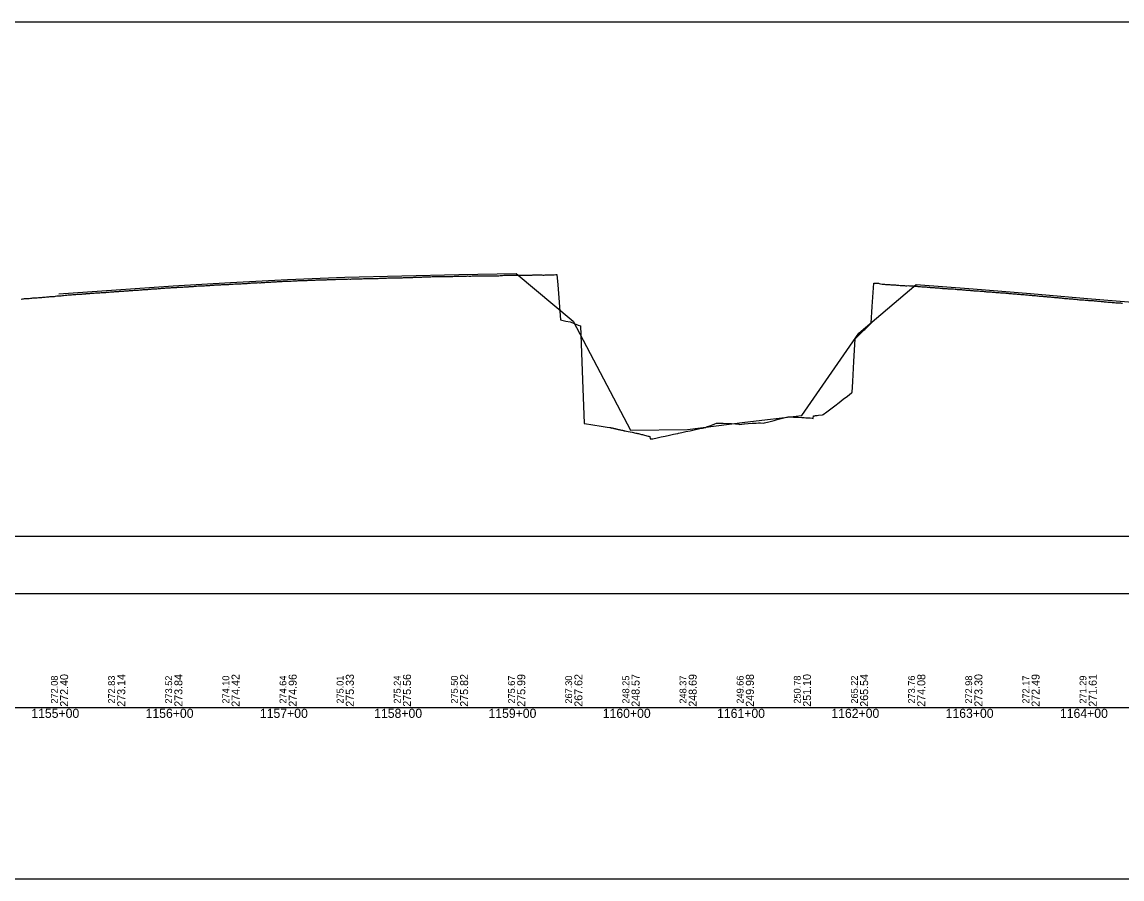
# Model space of a CAD drawing. Extents: x 2898 to 49495, y -15038 to -13538.
# Drawn here: x 4821 to 5783, y -15038 to -14288 of the extents above; entities that cross this region are included whole.
import ezdxf

# ---------------------------------------------------------------- set-up
doc = ezdxf.new("R2010")
doc.units = 0
for name, color, linetype in [('RD_DDB_Profile_EX', 7, 'Continuous'), ('RD_DDB_Profile_PR', 7, 'Continuous'), ('RD_DDB_StaTX', 7, 'Continuous'), ('RD_DDB_StripGrade', 7, 'Continuous'), ('RD_GPK_Profile_Cell', 7, 'Continuous'), ('RD_SHT_ShtClip', 7, 'Continuous')]:
    doc.layers.add(name, color=color, linetype=linetype)

msp = doc.modelspace()

# ---------------------------------------------------------------- linework, layer by layer
at = {"layer": 'RD_DDB_Profile_EX'}
for points in [[(5085.43, -14513.98), (5086.43, -14513.98), (5086.86, -14513.98), (5087.43, -14513.98), (5088.43, -14513.93), (5089.43, -14513.83), (5090.49, -14513.78), (5091.43, -14513.78), (5092.43, -14513.73), (5093.43, -14513.73), (5094.43, -14513.68), (5095.43, -14513.68), (5096.43, -14513.64), (5097.78, -14513.53), (5098.76, -14513.53), (5099.76, -14513.53), (5100.78, -14513.47), (5101.35, -14513.47), (5101.76, -14513.47), (5102.76, -14513.42), (5103.76, -14513.41), (5104.97, -14513.41), (5105.76, -14513.4), (5106.76, -14513.35), (5107.76, -14513.4), (5108.76, -14513.39), (5109.76, -14513.34), (5110.76, -14513.29), (5111.76, -14513.29), (5112.22, -14513.29), (5112.76, -14513.29), (5113.76, -14513.24), (5114.76, -14513.19), (5115.84, -14513.18), (5116.77, -14513.18), (5117.77, -14513.18), (5118.77, -14513.13), (5119.77, -14513.08), (5120.77, -14513.08), (5121.77, -14513.08), (5122.77, -14513.03), (5123.08, -14513.02), (5123.77, -14512.98), (5124.77, -14512.98), (5125.77, -14512.99), (5126.77, -14512.89), (5127.77, -14512.94), (5128.77, -14512.94), (5129.77, -14512.89), (5130.33, -14512.87), (5130.77, -14512.84), (5131.75, -14512.8), (5132.75, -14512.8), (5133.95, -14512.79), (5134.75, -14512.76), (5135.75, -14512.66), (5136.27, -14512.64), (5137.19, -14512.6), (5137.57, -14512.58), (5138.12, -14512.56), (5139.03, -14512.56), (5139.94, -14512.56), (5141.19, -14512.48), (5141.85, -14512.47), (5142.76, -14512.47), (5143.68, -14512.46), (5144.82, -14512.41), (5145.55, -14512.4), (5146.51, -14512.49), (5146.87, -14512.49), (5147.88, -14512.48), (5148.44, -14512.42), (5148.87, -14512.38), (5149.87, -14512.32), (5150.88, -14512.32), (5152.06, -14512.3), (5152.87, -14512.26), (5153.86, -14512.25), (5154.87, -14512.2), (5155.87, -14512.19), (5156.86, -14512.14), (5157.87, -14512.14), (5158.87, -14512.13), (5159.3, -14512.09), (5159.86, -14512.03), (5160.87, -14511.98), (5161.86, -14511.97), (5162.93, -14511.97), (5163.87, -14511.91), (5164.9, -14511.91), (5165.87, -14511.86), (5166.55, -14511.82), (5166.87, -14511.81), (5167.87, -14511.81), (5168.87, -14511.75), (5170.17, -14511.7), (5170.87, -14511.7), (5171.87, -14511.6), (5172.86, -14511.6), (5173.87, -14511.6), (5174.87, -14511.6)], [(5174.87, -14511.6), (5175.86, -14511.55), (5176.87, -14511.4), (5177.41, -14511.4), (5177.87, -14511.4), (5178.87, -14511.35), (5179.87, -14511.2), (5181.04, -14511.2), (5181.87, -14511.2), (5182.87, -14511.19), (5183.87, -14511.18), (5184.88, -14511.12), (5185.88, -14511.16), (5186.88, -14511.15), (5187.87, -14511.14), (5188.28, -14511.16), (5188.88, -14511.18), (5189.88, -14511.13), (5190.88, -14511.12), (5191.9, -14511.11), (5192.88, -14511.1), (5193.89, -14511.09), (5194.89, -14511.08), (5195.52, -14511.08), (5195.89, -14511.07), (5196.89, -14511.07), (5197.89, -14511.06), (5199.15, -14510.99), (5199.89, -14510.95), (5200.89, -14510.9), (5201.89, -14510.89), (5202.89, -14510.93), (5203.9, -14510.98), (5204.89, -14510.97), (5205.9, -14510.97), (5206.39, -14510.89), (5206.9, -14510.82), (5207.9, -14510.81), (5208.9, -14510.85), (5210.01, -14510.84), (5210.9, -14510.75), (5211.9, -14510.8), (5212.9, -14510.84), (5213.9, -14510.79), (5214.9, -14510.69), (5215.9, -14510.64), (5216.9, -14510.64), (5217.26, -14510.64), (5217.9, -14510.64), (5218.9, -14510.64), (5219.91, -14510.59), (5220.9, -14510.53), (5221.9, -14510.58), (5222.91, -14510.59), (5223.32, -14510.58), (5224.5, -14510.52), (5225.32, -14510.51), (5226.34, -14510.56), (5227.34, -14510.59), (5228.35, -14510.64), (5229.35, -14510.67), (5230.35, -14510.71), (5231.35, -14510.66), (5231.74, -14510.65), (5232.35, -14510.65), (5233.35, -14510.64), (5234.35, -14510.55), (5235.37, -14510.54), (5236.35, -14510.58), (5237.35, -14510.52), (5238.35, -14510.48), (5239.35, -14510.37), (5240.35, -14510.28), (5241.36, -14510.19), (5242.61, -14510.16), (5243.36, -14510.12), (5244.36, -14510.11), (5245.36, -14510.15), (5246.44, -14510.07), (5247.36, -14510.02), (5248.36, -14510.02), (5249.36, -14510.06), (5249.85, -14510.08), (5250.36, -14510.1), (5251.36, -14510.14), (5252.36, -14510.1), (5253.47, -14510.14), (5254.36, -14510.09), (5255.36, -14510.04), (5256.36, -14510), (5257.35, -14510.04), (5258.35, -14510), (5259.35, -14509.94), (5260.35, -14509.94), (5260.72, -14509.96), (5261.35, -14509.98), (5262.35, -14509.89), (5263.35, -14509.89), (5264.35, -14509.89), (5265.35, -14509.94), (5266.35, -14509.94)], [(5266.35, -14509.94), (5267.35, -14509.89), (5267.96, -14509.86), (5268.35, -14509.84), (5269.35, -14509.84), (5270.43, -14509.85), (5270.81, -14509.84), (5271.81, -14509.78), (5272.81, -14509.81), (5273.81, -14509.83), (5274.82, -14509.81), (5275.21, -14509.82), (5275.82, -14509.84), (5276.82, -14509.9), (5277.82, -14509.89), (5278.83, -14509.8), (5279.84, -14509.75), (5280.84, -14509.83), (5281.83, -14509.78), (5282.83, -14509.81), (5283.84, -14509.83), (5286.77, -14509.85), (5288.18, -14509.53), (5289.08, -14509.51), (5289.79, -14518.35), (5292.26, -14549.19), (5293.32, -14549.42), (5296.94, -14550.21), (5300.56, -14551.01), (5301.47, -14551.21), (5304.18, -14552.28), (5307.8, -14553.71), (5309.67, -14554.45), (5311.43, -14601.52), (5312.85, -14639.84), (5315.05, -14640.17), (5318.67, -14640.71), (5322.29, -14641.26), (5325.91, -14641.82), (5329.54, -14642.38), (5333.16, -14642.95), (5335.26, -14643.28), (5335.61, -14643.35), (5335.98, -14643.41), (5336.36, -14643.49), (5336.78, -14643.69), (5337.16, -14643.84), (5337.58, -14643.76), (5338.02, -14643.91), (5338.47, -14644.01), (5338.94, -14644.14), (5339.43, -14644.2), (5339.94, -14644.29), (5340.46, -14644.38), (5341.01, -14644.5), (5341.57, -14644.66), (5342.17, -14644.81), (5342.79, -14645.01), (5343.44, -14645.13), (5344.11, -14645.28), (5344.82, -14645.44), (5345.56, -14645.61), (5346.34, -14645.76), (5347.16, -14645.94), (5347.65, -14646.06), (5348.02, -14646.14), (5348.92, -14646.35), (5349.88, -14646.57), (5351.27, -14646.83), (5354.89, -14647.53), (5358.15, -14648.16), (5358.51, -14648.23), (5358.89, -14648.31), (5359.64, -14648.5), (5360.43, -14648.71), (5361.23, -14648.92), (5362.13, -14649.14), (5362.94, -14649.32), (5363.85, -14649.55), (5364.78, -14649.79), (5365.76, -14650.05), (5366.76, -14650.26), (5367.82, -14650.54), (5368.91, -14650.82), (5369.38, -14650.95), (5370.42, -14651.15), (5370.75, -14653.27), (5371.36, -14653.28), (5372.27, -14653.29), (5373.07, -14653.12), (5376.69, -14652.34), (5380.24, -14651.57), (5383.87, -14650.79), (5387.49, -14650.01), (5391.11, -14649.23), (5392.72, -14648.88), (5394.73, -14648.45), (5395.6, -14648.27), (5398.35, -14647.68), (5401.98, -14646.91), (5405.6, -14646.14)], [(4905.28, -14524.2), (4905.77, -14524.18), (4906.3, -14524.16), (4907.3, -14524.06), (4908.28, -14523.97), (4909.39, -14523.97), (4910.11, -14523.92), (4911.13, -14523.87), (4912.12, -14523.77), (4913.12, -14523.72), (4914.14, -14523.67), (4915.12, -14523.56), (4916.14, -14523.51), (4916.63, -14523.46), (4917.11, -14523.42), (4918.11, -14523.32), (4919.11, -14523.26), (4920.25, -14523.2), (4921.11, -14523.12), (4922.12, -14523.07), (4923.12, -14523.02), (4924.11, -14522.92), (4925.14, -14522.82), (4926.11, -14522.72), (4927.13, -14522.62), (4927.5, -14522.61), (4928.11, -14522.57), (4929.11, -14522.48), (4930.11, -14522.48), (4931.12, -14522.43), (4932.11, -14522.28), (4933.11, -14522.29), (4934.12, -14522.19), (4934.74, -14522.13), (4935.11, -14522.1), (4936.11, -14522.05), (4937.11, -14521.95), (4938.36, -14521.86), (4939.11, -14521.86), (4940.12, -14521.82), (4941.11, -14521.62), (4942.11, -14521.58), (4943.1, -14521.53), (4944.11, -14521.39), (4945.11, -14521.4), (4945.61, -14521.35), (4946.11, -14521.3), (4946.83, -14521.25), (4947.84, -14521.15), (4948.83, -14521.15), (4949.23, -14521.15), (4949.83, -14521.15), (4950.83, -14521), (4951.83, -14520.9), (4952.85, -14520.9), (4953.83, -14520.85), (4954.83, -14520.75), (4955.83, -14520.76), (4956.47, -14520.69), (4956.83, -14520.66), (4957.83, -14520.66), (4958.83, -14520.66), (4960.1, -14520.59), (4960.83, -14520.52), (4961.83, -14520.42), (4962.83, -14520.37), (4963.83, -14520.32), (4964.83, -14520.18), (4965.83, -14520.18), (4966.83, -14520.13), (4967.34, -14520.06), (4967.83, -14519.99), (4968.83, -14519.99), (4969.83, -14519.89), (4970.96, -14519.83), (4971.84, -14519.66), (4972.84, -14519.66), (4973.84, -14519.57), (4974.84, -14519.47), (4975.83, -14519.48), (4976.83, -14519.43), (4977.84, -14519.39), (4978.21, -14519.37), (4978.83, -14519.35), (4979.84, -14519.25), (4980.83, -14519.26), (4981.83, -14519.16), (4982.83, -14519.07), (4983.89, -14519.02), (4984.89, -14519.01), (4985.45, -14518.96), (4985.89, -14518.91), (4986.89, -14518.86), (4987.89, -14518.86), (4989.07, -14518.73), (4989.89, -14518.61), (4990.88, -14518.51), (4991.88, -14518.5), (4992.89, -14518.55), (4993.89, -14518.45), (4994.89, -14518.4)], [(4994.89, -14518.4), (4995.89, -14518.3), (4996.32, -14518.3), (4996.89, -14518.3), (4997.89, -14518.3), (4998.89, -14518.25), (4999.94, -14518.2), (5000.89, -14518.25), (5001.89, -14518.2), (5002.89, -14518), (5003.56, -14517.97), (5003.9, -14517.95), (5004.9, -14517.96), (5005.89, -14517.91), (5007.18, -14517.74), (5007.91, -14517.71), (5008.9, -14517.66), (5009.9, -14517.57), (5010.9, -14517.57), (5011.9, -14517.57), (5012.9, -14517.47), (5013.9, -14517.43), (5014.43, -14517.4), (5014.9, -14517.38), (5015.9, -14517.29), (5016.9, -14517.24), (5018.05, -14517.18), (5018.9, -14517.1), (5019.9, -14517.11), (5020.91, -14516.91), (5021.91, -14516.87), (5022.91, -14516.82), (5023.88, -14516.83), (5024.65, -14516.78), (5025.29, -14516.71), (5025.66, -14516.68), (5026.66, -14516.62), (5027.65, -14516.57), (5028.91, -14516.61), (5029.65, -14516.61), (5030.65, -14516.55), (5031.66, -14516.4), (5032.65, -14516.4), (5033.65, -14516.39), (5034.65, -14516.29), (5035.66, -14516.29), (5036.16, -14516.24), (5036.65, -14516.19), (5037.66, -14516.14), (5038.66, -14516.09), (5039.78, -14515.98), (5040.66, -14515.89), (5041.65, -14515.84), (5042.65, -14515.84), (5043.66, -14515.74), (5044.65, -14515.69), (5045.66, -14515.64), (5046.65, -14515.59), (5047.02, -14515.59), (5047.65, -14515.59), (5048.65, -14515.54), (5049.66, -14515.39), (5050.66, -14515.39), (5051.66, -14515.4), (5052.66, -14515.35), (5053.66, -14515.25), (5054.27, -14515.25), (5054.67, -14515.25), (5055.67, -14515.25), (5056.66, -14515.15), (5057.89, -14515.05), (5058.66, -14515.02), (5059.66, -14514.97), (5060.66, -14514.88), (5061.67, -14514.88), (5062.67, -14514.83), (5063.67, -14514.79), (5064.67, -14514.79), (5065.45, -14514.64), (5066.45, -14514.63), (5067.45, -14514.63), (5068.45, -14514.62), (5068.75, -14514.62), (5069.45, -14514.62), (5070.45, -14514.61), (5071.45, -14514.51), (5072.45, -14514.51), (5073.45, -14514.45), (5074.44, -14514.45), (5075.44, -14514.4), (5076, -14514.37), (5076.44, -14514.34), (5077.44, -14514.29), (5078.44, -14514.24), (5079.62, -14514.19), (5080.44, -14514.18), (5081.44, -14514.23), (5082.43, -14514.18), (5083.43, -14514.13), (5084.43, -14514.08), (5085.43, -14513.98)], [(5405.6, -14646.14), (5409.22, -14645.36), (5412.84, -14644.59), (5414, -14644.34), (5416.46, -14643.81), (5419.04, -14643.26), (5420.09, -14642.86), (5423.71, -14641.49), (5427.33, -14640.12), (5428.82, -14639.55), (5429.16, -14639.41), (5430.95, -14639.47), (5434.57, -14639.6), (5438.19, -14639.73), (5440.74, -14639.78), (5441.82, -14639.88), (5445.44, -14640.22), (5448.13, -14640.47), (5449.06, -14640.59), (5452.68, -14640.22), (5453.09, -14640.18), (5456.3, -14639.94), (5459.93, -14639.67), (5463.55, -14639.4), (5465.36, -14639.26), (5467.17, -14639.31), (5470.05, -14639.4), (5470.79, -14639.21), (5474.41, -14638.29), (5478.04, -14637.37), (5479.04, -14637.12), (5481.66, -14636.43), (5485.28, -14635.47), (5488.9, -14634.51), (5491.14, -14633.92), (5492.52, -14633.97), (5493.87, -14634.02), (5496.15, -14634.15), (5499.77, -14634.35), (5503.39, -14634.56), (5505.49, -14634.68), (5507.01, -14634.76), (5510.32, -14634.95), (5510.63, -14634.97), (5512.45, -14635.27), (5513.22, -14635.46), (5513.63, -14633.16), (5514.33, -14633.07), (5514.86, -14633.01), (5515.33, -14632.91), (5515.74, -14632.87), (5516.1, -14632.82), (5516.71, -14632.76), (5517.88, -14632.6), (5521.5, -14632.14), (5521.97, -14632.08), (5525.12, -14629.71), (5528.74, -14626.99), (5532.37, -14624.25), (5535.99, -14621.45), (5539.61, -14618.64), (5543.23, -14615.83), (5546.85, -14613.01), (5547.43, -14612.57), (5547.92, -14603.01), (5548.84, -14585.62), (5549.89, -14565.69), (5550.48, -14565.13), (5554.1, -14561.68), (5557.72, -14558.23), (5558.39, -14557.59), (5561.34, -14554.61), (5564.02, -14551.91), (5564.96, -14537.4), (5566.38, -14516.89), (5566.92, -14516.9), (5567.47, -14516.91), (5568.04, -14516.94), (5568.61, -14517.01), (5569.19, -14517.05), (5569.78, -14517.08), (5570.39, -14517.13), (5571.02, -14517.2), (5572.21, -14517.48), (5573.76, -14517.85), (5574.7, -14517.94), (5575.83, -14518.02), (5576.56, -14518.1), (5577.51, -14518.15), (5578.44, -14518.16), (5579.45, -14518.22), (5580.34, -14518.32), (5581.29, -14518.42), (5582.33, -14518.43), (5583.29, -14518.48), (5584.28, -14518.5), (5585.32, -14518.56), (5586.29, -14518.76), (5586.7, -14518.79), (5587.28, -14518.83), (5588.32, -14518.84)], [(5588.32, -14518.84), (5589.29, -14518.99), (5590.32, -14519.06), (5591.29, -14519.12), (5592.28, -14519.13), (5593.28, -14519.19), (5593.94, -14519.23), (5594.29, -14519.26), (5595.28, -14519.22), (5596.28, -14519.18), (5597.56, -14519.26), (5598.28, -14519.3), (5599.28, -14519.42), (5600.28, -14519.38), (5601.18, -14519.43), (5602.15, -14519.57), (5602.65, -14519.62), (5603.14, -14519.66), (5604.14, -14519.71), (5604.81, -14519.81), (5605.14, -14519.86), (5606.14, -14519.95), (5607.14, -14520.05), (5608.43, -14520.13), (5609.14, -14520.24), (5610.14, -14520.29), (5611.14, -14520.28), (5612.15, -14520.38), (5613.14, -14520.43), (5614.14, -14520.57), (5615.15, -14520.67), (5615.67, -14520.75), (5616.14, -14520.82), (5617.14, -14520.87), (5618.14, -14520.87), (5619.29, -14520.94), (5620.16, -14521.06), (5621.14, -14521.06), (5622.14, -14521.16), (5623.14, -14521.21), (5624.14, -14521.31), (5625.14, -14521.41), (5626.14, -14521.51), (5626.54, -14521.55), (5627.14, -14521.61), (5628.13, -14521.66), (5629.13, -14521.71), (5630.16, -14521.76), (5631.14, -14521.91), (5632.15, -14522.06), (5633.14, -14522.06), (5633.78, -14522.09), (5634.14, -14522.11), (5635.13, -14522.12), (5636.14, -14522.12), (5637.4, -14522.22), (5638.15, -14522.37), (5639.15, -14522.47), (5640.15, -14522.58), (5641.14, -14522.63), (5642.14, -14522.69), (5642.98, -14522.68), (5643.98, -14522.78), (5644.65, -14522.84), (5644.98, -14522.87), (5645.98, -14522.91), (5646.98, -14523.01), (5648.27, -14523.15), (5648.98, -14523.25), (5649.99, -14523.29), (5650.98, -14523.39), (5651.99, -14523.44), (5652.99, -14523.53), (5653.98, -14523.63), (5654.99, -14523.68), (5655.51, -14523.7), (5655.99, -14523.73), (5656.98, -14523.77), (5657.99, -14523.82), (5659.13, -14523.98), (5659.99, -14524.07), (5660.99, -14524.07), (5661.99, -14524.07), (5662.99, -14524.31), (5663.99, -14524.41), (5664.98, -14524.51), (5665.99, -14524.51), (5666.38, -14524.53), (5666.99, -14524.56), (5667.99, -14524.66), (5668.99, -14524.75), (5670, -14524.85), (5670.99, -14524.9), (5671.99, -14524.96), (5672.99, -14525.05), (5673.62, -14525.12), (5673.99, -14525.16), (5674.99, -14525.16), (5675.99, -14525.26), (5677.24, -14525.37), (5677.98, -14525.41)], [(4820.37, -14530.94), (4821.37, -14530.84), (4822.46, -14530.68), (4823.36, -14530.58), (4824.37, -14530.58), (4825.41, -14530.52), (4826.4, -14530.41), (4827.41, -14530.31), (4828.41, -14530.16), (4829.4, -14530.11), (4829.71, -14530.08), (4830.41, -14530), (4831.41, -14529.91), (4832.4, -14529.9), (4833.41, -14529.85), (4834.41, -14529.75), (4835.4, -14529.59), (4836.41, -14529.49), (4836.95, -14529.46), (4837.41, -14529.44), (4838.4, -14529.44), (4839.41, -14529.38), (4840.57, -14529.31), (4841.4, -14529.19), (4842.41, -14529.09), (4843.4, -14529.03), (4844.41, -14528.89), (4845.41, -14528.84), (4846.4, -14528.74), (4847.41, -14528.64), (4847.82, -14528.6), (4848.41, -14528.55), (4849.4, -14528.55), (4850.4, -14528.4), (4851.44, -14528.25), (4852.4, -14528.2), (4853.4, -14528.06), (4854.4, -14528.01), (4855.39, -14527.97), (4856.4, -14527.82), (4857.4, -14527.78), (4858.68, -14527.65), (4859.4, -14527.58), (4860.39, -14527.49), (4861.39, -14527.34), (4862.4, -14527.3), (4863.39, -14527.3), (4864.39, -14527.2), (4865.39, -14527.01), (4865.92, -14526.96), (4866.37, -14526.92), (4867.37, -14526.82), (4868.28, -14526.82), (4869.55, -14526.76), (4870.28, -14526.72), (4871.28, -14526.61), (4872.28, -14526.51), (4873.28, -14526.51), (4874.28, -14526.46), (4875.28, -14526.35), (4876.28, -14526.3), (4876.79, -14526.22), (4877.28, -14526.15), (4878.28, -14526.1), (4879.28, -14526.05), (4880.41, -14525.97), (4881.28, -14525.85), (4882.28, -14525.8), (4883.28, -14525.74), (4884.28, -14525.65), (4885.28, -14525.59), (4886.28, -14525.54), (4887.28, -14525.49), (4887.66, -14525.46), (4888.28, -14525.4), (4889.28, -14525.35), (4890.28, -14525.25), (4891.28, -14525.2), (4892.28, -14525.2), (4893.28, -14525.11), (4894.28, -14525.06), (4894.9, -14524.93), (4895.28, -14524.86), (4896.28, -14524.77), (4897.28, -14524.77), (4898.52, -14524.71), (4899.28, -14524.67), (4900.28, -14524.72), (4901.28, -14524.58), (4902.28, -14524.39), (4903.31, -14524.34), (4904.3, -14524.34), (4905.28, -14524.2)], [(5677.98, -14525.41), (5678.99, -14525.46), (5679.99, -14525.52), (5681, -14525.62), (5681.99, -14525.67), (5682.99, -14525.82), (5683.99, -14525.88), (5684.49, -14525.93), (5684.91, -14525.97), (5685.9, -14526.12), (5686.91, -14526.17), (5688.11, -14526.25), (5688.91, -14526.32), (5689.9, -14526.43), (5690.9, -14526.47), (5691.9, -14526.57), (5692.9, -14526.63), (5693.9, -14526.78), (5694.9, -14526.83), (5695.35, -14526.83), (5695.91, -14526.83), (5696.9, -14526.89), (5697.9, -14527.04), (5698.98, -14527.15), (5699.9, -14527.24), (5700.9, -14527.29), (5701.9, -14527.44), (5702.89, -14527.54), (5703.9, -14527.65), (5704.89, -14527.75), (5705.89, -14527.8), (5706.22, -14527.84), (5706.9, -14527.91), (5707.89, -14527.96), (5708.9, -14528.11), (5709.89, -14528.22), (5710.89, -14528.27), (5711.89, -14528.33), (5712.89, -14528.48), (5713.46, -14528.51), (5713.88, -14528.54), (5714.89, -14528.64), (5715.89, -14528.7), (5717.09, -14528.81), (5717.89, -14528.86), (5718.88, -14528.96), (5719.38, -14529.02), (5719.89, -14529.07), (5720.88, -14529.07), (5721.88, -14529.18), (5722.88, -14529.28), (5723.19, -14529.33), (5724.33, -14529.5), (5725.19, -14529.62), (5726.19, -14529.67), (5727.26, -14529.67), (5728.19, -14529.76), (5729.19, -14529.86), (5730.19, -14529.9), (5731.19, -14530.05), (5731.57, -14530.13), (5732.19, -14530.25), (5733.19, -14530.35), (5734.19, -14530.39), (5735.2, -14530.44), (5736.19, -14530.49), (5737.19, -14530.63), (5738.19, -14530.73), (5738.82, -14530.76), (5739.19, -14530.78), (5740.19, -14530.88), (5741.19, -14530.98), (5742.44, -14531), (5743.2, -14531.08), (5744.19, -14531.22), (5745.19, -14531.32), (5746.19, -14531.47), (5747.19, -14531.47), (5748.19, -14531.57), (5749.19, -14531.62), (5749.68, -14531.64), (5750.19, -14531.67), (5751.2, -14531.82), (5752.19, -14531.92), (5753.31, -14532.03), (5754.19, -14532.07), (5755.19, -14532.07), (5756.19, -14532.22), (5757.19, -14532.27), (5758.2, -14532.33), (5759.2, -14532.43), (5760.19, -14532.53), (5760.55, -14532.57), (5761.2, -14532.63), (5762.2, -14532.73), (5763.2, -14532.83), (5764.19, -14532.89), (5765.19, -14532.99), (5766.02, -14533.09), (5767.04, -14533.19), (5768.03, -14533.23)], [(5768.03, -14533.23), (5769.03, -14533.38), (5770.02, -14533.48), (5771.03, -14533.53), (5771.42, -14533.56), (5772.03, -14533.62), (5773.04, -14533.68), (5774.03, -14533.77), (5775.04, -14533.87), (5776.02, -14533.87), (5777.03, -14533.97), (5778.02, -14534.12), (5778.66, -14534.15), (5779.04, -14534.17), (5780.03, -14534.17), (5781.02, -14534.27), (5782.28, -14534.34), (5783.03, -14534.42), (5784.02, -14534.52)]]:
    msp.add_lwpolyline(points, dxfattribs=at)
at = {"layer": 'RD_DDB_Profile_PR'}
msp.add_lwpolyline([(4853.38, -14526.46), (4903.38, -14522.74), (4953.38, -14519.28), (5003.38, -14516.38), (5053.38, -14513.68), (5103.38, -14511.81), (5153.38, -14510.65), (5203.38, -14509.35), (5253.38, -14508.53), (5303.38, -14550.36), (5353.38, -14645.64), (5403.38, -14645.01), (5453.38, -14638.56), (5503.38, -14632.96), (5553.38, -14560.76), (5603.38, -14518.07), (5653.38, -14521.97), (5703.38, -14525.99), (5753.38, -14530.43), (5803.38, -14534.48)], dxfattribs=at)
at = {"layer": 'RD_GPK_Profile_Cell'}
msp.add_line((2976.05, -14888.47), (48721.13, -14888.47), dxfattribs=at)
at = {"layer": 'RD_SHT_ShtClip'}
for points in [[(5976.22, -14788.47), (5976.22, -14288.47), (5976.22, -14288.47), (4476.38, -14288.47), (4476.38, -14788.47)], [(4456.38, -14738.47), (5996.05, -14738.47), (5996.05, -15038.47), (4456.38, -15038.47)]]:
    msp.add_lwpolyline(points, close=True, dxfattribs=at)

# ---------------------------------------------------------------- texts
at = {"layer": 'RD_DDB_StaTX'}
for s, p in [('1155+00', (4829.18, -14897.47)), ('1156+00', (4929.18, -14897.47)), ('1157+00', (5029.18, -14897.47)), ('1158+00', (5129.18, -14897.47)), ('1159+00', (5229.18, -14897.47)), ('1160+00', (5329.18, -14897.47)), ('1161+00', (5429.18, -14897.47)), ('1162+00', (5529.18, -14897.47)), ('1163+00', (5629.18, -14897.47)), ('1164+00', (5729.18, -14897.47))]:
    msp.add_text(s, height=8, dxfattribs=at).set_placement(p)
at = {"layer": 'RD_DDB_StripGrade'}
for s, height, p in [('272.40', 7, (4861.38, -14887.72)), ('273.14', 7, (4911.38, -14887.72)), ('273.84', 7, (4961.38, -14887.72)), ('274.42', 7, (5011.38, -14887.72)), ('274.96', 7, (5061.38, -14887.72)), ('275.33', 7, (5111.38, -14887.72)), ('275.56', 7, (5161.38, -14887.72)), ('275.82', 7, (5211.38, -14887.72)), ('275.99', 7, (5261.38, -14887.72)), ('267.62', 7, (5311.38, -14887.72)), ('248.57', 7, (5361.38, -14887.72)), ('248.69', 7, (5411.38, -14887.72)), ('249.98', 7, (5461.38, -14887.72)), ('251.10', 7, (5511.38, -14887.72)), ('265.54', 7, (5561.38, -14887.72)), ('274.08', 7, (5611.38, -14887.72)), ('273.30', 7, (5661.38, -14887.72)), ('272.49', 7, (5711.38, -14887.72)), ('271.61', 7, (5761.38, -14887.72)), ('272.08', 6, (4852.38, -14884.98)), ('272.83', 6, (4902.38, -14884.98)), ('273.52', 6, (4952.38, -14884.98)), ('274.10', 6, (5002.38, -14884.98)), ('274.64', 6, (5052.38, -14884.98)), ('275.01', 6, (5102.38, -14884.98)), ('275.24', 6, (5152.38, -14884.98)), ('275.50', 6, (5202.38, -14884.98)), ('275.67', 6, (5252.38, -14884.98)), ('267.30', 6, (5302.38, -14884.98)), ('248.25', 6, (5352.38, -14884.98)), ('248.37', 6, (5402.38, -14884.98)), ('249.66', 6, (5452.38, -14884.98)), ('250.78', 6, (5502.38, -14884.98)), ('265.22', 6, (5552.38, -14884.98)), ('273.76', 6, (5602.38, -14884.98)), ('272.98', 6, (5652.38, -14884.98)), ('272.17', 6, (5702.38, -14884.98)), ('271.29', 6, (5752.38, -14884.98))]:
    msp.add_text(s, height=height, rotation=90, dxfattribs=at).set_placement(p)

doc.saveas('drawing.dxf')
